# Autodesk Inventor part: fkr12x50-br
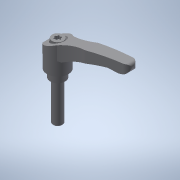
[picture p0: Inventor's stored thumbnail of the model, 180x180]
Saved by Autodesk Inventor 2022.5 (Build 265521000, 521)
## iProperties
Created: 2017-09
Part Number: fkr12x50-br
Material: 一般
Document SubType Name: Modeling
Designer: imaocorp
Density: 1 g/cm^3
Appearance: 既定
Author: imaocorp
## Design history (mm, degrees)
node "fkr12x50-br.x_t1"
node "fkr12x50-br"
node "Base1"
